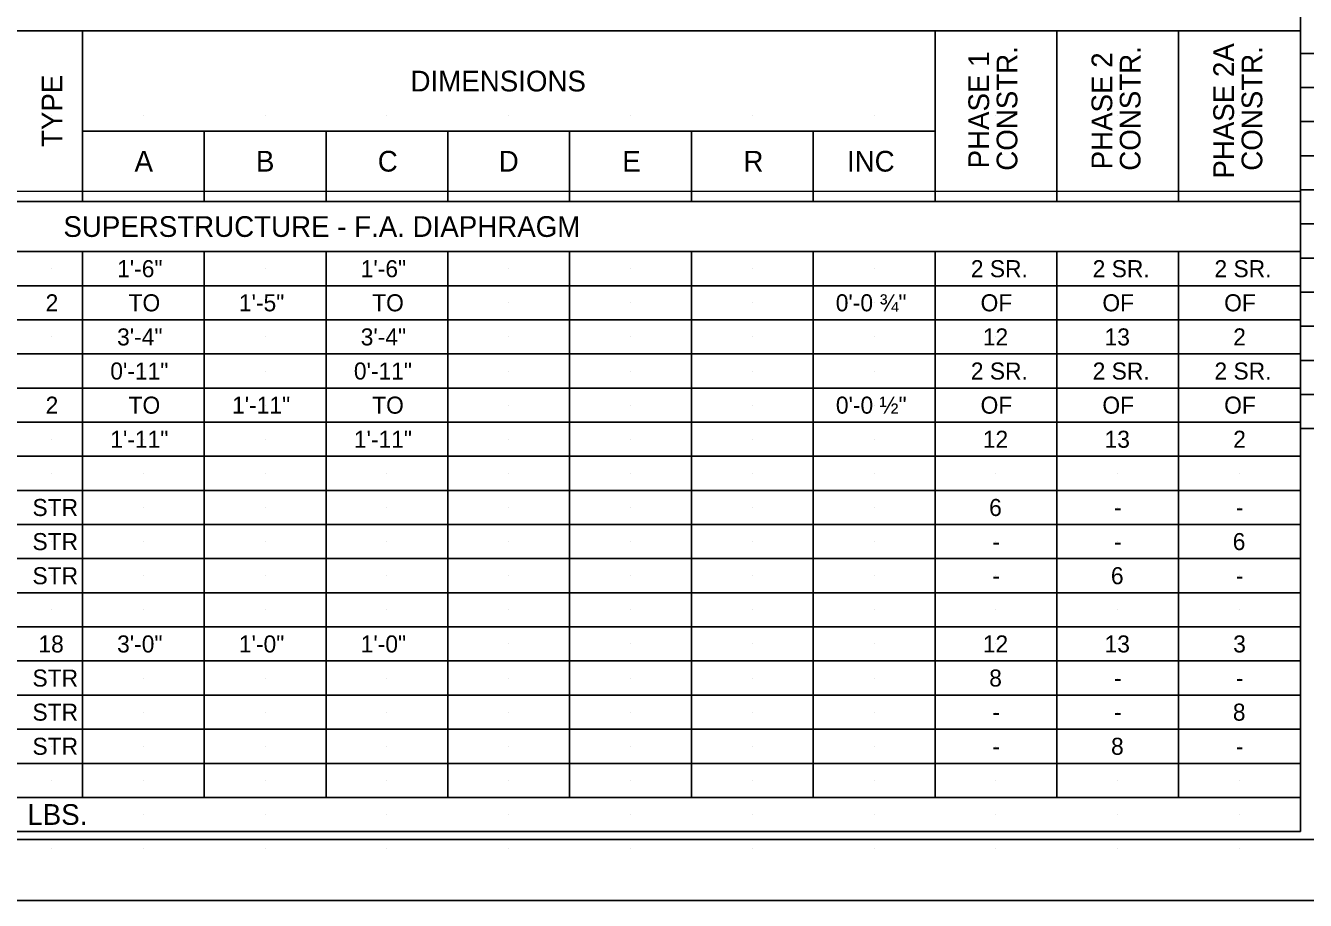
# Model space of a CAD drawing. Extents: x 0 to 34, y 0 to 22.
# Drawn here: x 6.29 to 16.8, y 0 to 7.18 of the extents above; entities that cross this region are included whole.
import ezdxf

# ---------------------------------------------------------------- set-up
doc = ezdxf.new("R2010")
doc.units = 0
for name, color, linetype in [('BR_P_Gen_Text', 7, 'Continuous'), ('SH_Border', 7, 'Continuous'), ('SH_Cut_Line', 7, 'Continuous')]:
    doc.layers.add(name, color=color, linetype=linetype)

msp = doc.modelspace()

# ---------------------------------------------------------------- linework, layer by layer
at = {"layer": 'BR_P_Gen_Text'}
for p, q in [((16.76, 3.872), (16.76, 14.272)), ((1.593, 7.137), (16.76, 7.137)), ((6.76, 5.737), (6.76, 7.137)), ((13.76, 5.737), (13.76, 7.137)), ((14.76, 5.737), (14.76, 7.137)), ((15.76, 5.737), (15.76, 7.137)), ((16.76, 0.565), (16.76, 7.137)), ((16.76, 0.565), (16.76, 7.137)), ((16.76, 6.952), (31.927, 6.952)), ((16.76, 6.672), (31.927, 6.672)), ((6.51, 6.441), (6.51, 6.441)), ((6.51, 6.441), (6.51, 6.441)), ((7.26, 6.441), (7.26, 6.441)), ((8.26, 6.441), (8.26, 6.441)), ((9.26, 6.441), (9.26, 6.441)), ((10.26, 6.441), (10.26, 6.441)), ((11.26, 6.441), (11.26, 6.441)), ((12.26, 6.441), (12.26, 6.441)), ((13.26, 6.441), (13.26, 6.441)), ((14.26, 6.441), (14.26, 6.441)), ((15.26, 6.441), (15.26, 6.441)), ((16.26, 6.441), (16.26, 6.441)), ((6.76, 6.314), (13.76, 6.314)), ((7.76, 5.737), (7.76, 6.314)), ((8.76, 5.737), (8.76, 6.314)), ((9.76, 5.737), (9.76, 6.314)), ((10.76, 5.737), (10.76, 6.314)), ((11.76, 5.737), (11.76, 6.314)), ((12.76, 5.737), (12.76, 6.314)), ((16.76, 6.392), (31.927, 6.392)), ((16.76, 6.112), (31.927, 6.112)), ((1.593, 5.819), (16.76, 5.82)), ((16.76, 5.832), (31.927, 5.832)), ((1.593, 5.737), (16.76, 5.737)), ((7.677, 5.531), (7.677, 5.531)), ((16.76, 5.552), (31.927, 5.552)), ((1.593, 5.325), (16.76, 5.326)), ((6.76, 0.845), (6.76, 5.325)), ((7.76, 0.845), (7.76, 5.325)), ((8.76, 0.845), (8.76, 5.325)), ((9.76, 0.845), (9.76, 5.325)), ((10.76, 0.845), (10.76, 5.325)), ((11.76, 0.845), (11.76, 5.325)), ((12.76, 0.845), (12.76, 5.325)), ((13.76, 0.845), (13.76, 5.325)), ((14.76, 0.845), (14.76, 5.325)), ((15.76, 0.845), (15.76, 5.325)), ((16.76, 5.272), (31.927, 5.272)), ((6.51, 5.185), (6.51, 5.185)), ((7.26, 5.185), (7.26, 5.185)), ((8.26, 5.185), (8.26, 5.185)), ((9.26, 5.185), (9.26, 5.185)), ((10.26, 5.185), (10.26, 5.185)), ((11.26, 5.185), (11.26, 5.185)), ((12.26, 5.185), (12.26, 5.185)), ((13.26, 5.185), (13.26, 5.185)), ((14.26, 5.185), (14.26, 5.185)), ((15.26, 5.185), (15.26, 5.185)), ((16.26, 5.185), (16.26, 5.185)), ((1.593, 5.045), (16.76, 5.045)), ((16.76, 4.992), (31.927, 4.992)), ((6.51, 4.905), (6.51, 4.905)), ((7.26, 4.905), (7.26, 4.905)), ((8.26, 4.905), (8.26, 4.905)), ((9.26, 4.905), (9.26, 4.905)), ((10.26, 4.905), (10.26, 4.905)), ((11.26, 4.905), (11.26, 4.905)), ((12.26, 4.905), (12.26, 4.905)), ((13.26, 4.905), (13.26, 4.905)), ((14.26, 4.905), (14.26, 4.905)), ((15.26, 4.905), (15.26, 4.905)), ((16.26, 4.905), (16.26, 4.905)), ((1.593, 4.765), (16.76, 4.765)), ((6.51, 4.625), (6.51, 4.625)), ((7.26, 4.625), (7.26, 4.625)), ((8.26, 4.625), (8.26, 4.625)), ((9.26, 4.625), (9.26, 4.625)), ((10.26, 4.625), (10.26, 4.625)), ((11.26, 4.625), (11.26, 4.625)), ((12.26, 4.625), (12.26, 4.625)), ((13.26, 4.625), (13.26, 4.625)), ((14.26, 4.625), (14.26, 4.625)), ((15.26, 4.625), (15.26, 4.625)), ((16.26, 4.625), (16.26, 4.625)), ((16.76, 4.712), (31.927, 4.712)), ((1.593, 4.485), (16.76, 4.485)), ((16.76, 4.432), (31.927, 4.432)), ((7.26, 4.345), (7.26, 4.345)), ((8.26, 4.345), (8.26, 4.345)), ((9.26, 4.345), (9.26, 4.345)), ((10.26, 4.345), (10.26, 4.345)), ((11.26, 4.345), (11.26, 4.345)), ((12.26, 4.345), (12.26, 4.345)), ((13.26, 4.345), (13.26, 4.345)), ((14.26, 4.345), (14.26, 4.345)), ((15.26, 4.345), (15.26, 4.345)), ((16.26, 4.345), (16.26, 4.345)), ((1.593, 4.205), (16.76, 4.205)), ((16.76, 4.152), (31.927, 4.152)), ((6.51, 4.065), (6.51, 4.065)), ((7.26, 4.065), (7.26, 4.065)), ((8.26, 4.065), (8.26, 4.065)), ((9.26, 4.065), (9.26, 4.065)), ((10.26, 4.065), (10.26, 4.065)), ((11.26, 4.065), (11.26, 4.065)), ((12.26, 4.065), (12.26, 4.065)), ((13.26, 4.065), (13.26, 4.065)), ((14.26, 4.065), (14.26, 4.065)), ((15.26, 4.065), (15.26, 4.065)), ((16.26, 4.065), (16.26, 4.065)), ((1.593, 3.925), (16.76, 3.925)), ((6.51, 3.785), (6.51, 3.785)), ((7.26, 3.785), (7.26, 3.785)), ((8.26, 3.785), (8.26, 3.785)), ((9.26, 3.785), (9.26, 3.785)), ((10.26, 3.785), (10.26, 3.785)), ((11.26, 3.785), (11.26, 3.785)), ((12.26, 3.785), (12.26, 3.785)), ((13.26, 3.785), (13.26, 3.785)), ((14.26, 3.785), (14.26, 3.785)), ((15.26, 3.785), (15.26, 3.785)), ((16.26, 3.785), (16.26, 3.785)), ((16.76, 3.872), (31.927, 3.872)), ((1.593, 3.645), (16.76, 3.645)), ((6.51, 3.505), (6.51, 3.505)), ((7.26, 3.505), (7.26, 3.505)), ((8.26, 3.505), (8.26, 3.505)), ((9.26, 3.505), (9.26, 3.505)), ((10.26, 3.505), (10.26, 3.505)), ((11.26, 3.505), (11.26, 3.505)), ((12.26, 3.505), (12.26, 3.505)), ((13.26, 3.505), (13.26, 3.505)), ((14.26, 3.505), (14.26, 3.505)), ((15.26, 3.505), (15.26, 3.505)), ((16.26, 3.505), (16.26, 3.505)), ((1.593, 3.365), (16.76, 3.365)), ((6.51, 3.225), (6.51, 3.225)), ((6.51, 3.225), (6.51, 3.225)), ((7.26, 3.225), (7.26, 3.225)), ((7.26, 3.225), (7.26, 3.225)), ((8.26, 3.225), (8.26, 3.225)), ((8.26, 3.225), (8.26, 3.225)), ((9.26, 3.225), (9.26, 3.225)), ((9.26, 3.225), (9.26, 3.225)), ((10.26, 3.225), (10.26, 3.225)), ((10.26, 3.225), (10.26, 3.225)), ((11.26, 3.225), (11.26, 3.225)), ((11.26, 3.225), (11.26, 3.225)), ((12.26, 3.225), (12.26, 3.225)), ((12.26, 3.225), (12.26, 3.225)), ((13.26, 3.225), (13.26, 3.225)), ((13.26, 3.225), (13.26, 3.225)), ((14.26, 3.225), (14.26, 3.225)), ((15.26, 3.225), (15.26, 3.225)), ((16.26, 3.225), (16.26, 3.225)), ((1.593, 3.085), (16.76, 3.085)), ((6.51, 2.945), (6.51, 2.945)), ((6.51, 2.945), (6.51, 2.945)), ((7.26, 2.945), (7.26, 2.945)), ((7.26, 2.945), (7.26, 2.945)), ((8.26, 2.945), (8.26, 2.945)), ((8.26, 2.945), (8.26, 2.945)), ((9.26, 2.945), (9.26, 2.945)), ((9.26, 2.945), (9.26, 2.945)), ((10.26, 2.945), (10.26, 2.945)), ((10.26, 2.945), (10.26, 2.945)), ((11.26, 2.945), (11.26, 2.945)), ((11.26, 2.945), (11.26, 2.945)), ((12.26, 2.945), (12.26, 2.945)), ((12.26, 2.945), (12.26, 2.945)), ((13.26, 2.945), (13.26, 2.945)), ((13.26, 2.945), (13.26, 2.945)), ((14.26, 2.945), (14.26, 2.945)), ((14.26, 2.945), (14.26, 2.945)), ((15.26, 2.945), (15.26, 2.945)), ((15.26, 2.945), (15.26, 2.945)), ((16.26, 2.945), (16.26, 2.945)), ((16.26, 2.945), (16.26, 2.945)), ((1.593, 2.805), (16.76, 2.806)), ((6.51, 2.665), (6.51, 2.665)), ((7.26, 2.665), (7.26, 2.665)), ((8.26, 2.665), (8.26, 2.665)), ((9.26, 2.665), (9.26, 2.665)), ((10.26, 2.665), (10.26, 2.665)), ((11.26, 2.665), (11.26, 2.665)), ((12.26, 2.665), (12.26, 2.665)), ((13.26, 2.665), (13.26, 2.665)), ((14.26, 2.665), (14.26, 2.665)), ((15.26, 2.665), (15.26, 2.665)), ((16.26, 2.665), (16.26, 2.665)), ((1.593, 2.525), (16.76, 2.525)), ((6.51, 2.385), (6.51, 2.385)), ((7.26, 2.385), (7.26, 2.385)), ((8.26, 2.385), (8.26, 2.385)), ((9.26, 2.385), (9.26, 2.385)), ((10.26, 2.385), (10.26, 2.385)), ((11.26, 2.385), (11.26, 2.385)), ((12.26, 2.385), (12.26, 2.385)), ((13.26, 2.385), (13.26, 2.385)), ((14.26, 2.385), (14.26, 2.385)), ((15.26, 2.385), (15.26, 2.385)), ((16.26, 2.385), (16.26, 2.385)), ((1.593, 2.245), (16.76, 2.245)), ((6.51, 2.105), (6.51, 2.105)), ((7.26, 2.105), (7.26, 2.105)), ((8.26, 2.105), (8.26, 2.105)), ((9.26, 2.105), (9.26, 2.105)), ((10.26, 2.105), (10.26, 2.105)), ((11.26, 2.105), (11.26, 2.105)), ((12.26, 2.105), (12.26, 2.105)), ((13.26, 2.105), (13.26, 2.105)), ((14.26, 2.105), (14.26, 2.105)), ((15.26, 2.105), (15.26, 2.105)), ((16.26, 2.105), (16.26, 2.105)), ((1.593, 1.965), (16.76, 1.965)), ((6.51, 1.825), (6.51, 1.825)), ((7.26, 1.825), (7.26, 1.825)), ((8.26, 1.825), (8.26, 1.825)), ((9.26, 1.825), (9.26, 1.825)), ((10.26, 1.825), (10.26, 1.825)), ((11.26, 1.825), (11.26, 1.825)), ((12.26, 1.825), (12.26, 1.825)), ((13.26, 1.825), (13.26, 1.825)), ((14.26, 1.825), (14.26, 1.825)), ((15.26, 1.825), (15.26, 1.825)), ((16.26, 1.825), (16.26, 1.825)), ((1.593, 1.685), (16.76, 1.685)), ((6.51, 1.545), (6.51, 1.545)), ((7.26, 1.545), (7.26, 1.545)), ((8.26, 1.545), (8.26, 1.545)), ((9.26, 1.545), (9.26, 1.545)), ((10.26, 1.545), (10.26, 1.545)), ((11.26, 1.545), (11.26, 1.545)), ((12.26, 1.545), (12.26, 1.545)), ((13.26, 1.545), (13.26, 1.545)), ((14.26, 1.545), (14.26, 1.545)), ((15.26, 1.545), (15.26, 1.545)), ((16.26, 1.545), (16.26, 1.545)), ((1.593, 1.405), (16.76, 1.405)), ((6.51, 1.265), (6.51, 1.265)), ((7.26, 1.265), (7.26, 1.265)), ((8.26, 1.265), (8.26, 1.265)), ((9.26, 1.265), (9.26, 1.265)), ((10.26, 1.265), (10.26, 1.265)), ((11.26, 1.265), (11.26, 1.265)), ((12.26, 1.265), (12.26, 1.265)), ((13.26, 1.265), (13.26, 1.265)), ((14.26, 1.265), (14.26, 1.265)), ((15.26, 1.265), (15.26, 1.265)), ((16.26, 1.265), (16.26, 1.265)), ((1.593, 1.125), (16.76, 1.125)), ((6.51, 0.985), (6.51, 0.985)), ((7.26, 0.985), (7.26, 0.985)), ((8.26, 0.985), (8.26, 0.985)), ((9.26, 0.985), (9.26, 0.985)), ((10.26, 0.985), (10.26, 0.985)), ((11.26, 0.985), (11.26, 0.985)), ((12.26, 0.985), (12.26, 0.985)), ((13.26, 0.985), (13.26, 0.985)), ((14.26, 0.985), (14.26, 0.985)), ((15.26, 0.985), (15.26, 0.985)), ((16.26, 0.985), (16.26, 0.985)), ((1.593, 0.845), (16.76, 0.845)), ((6.51, 0.705), (6.51, 0.705)), ((7.26, 0.705), (7.26, 0.705)), ((8.26, 0.705), (8.26, 0.705)), ((9.26, 0.705), (9.26, 0.705)), ((10.26, 0.705), (10.26, 0.705)), ((11.26, 0.705), (11.26, 0.705)), ((12.26, 0.705), (12.26, 0.705)), ((13.26, 0.705), (13.26, 0.705)), ((14.26, 0.705), (14.26, 0.705)), ((15.26, 0.705), (15.26, 0.705)), ((16.26, 0.705), (16.26, 0.705)), ((1.593, 0.565), (16.76, 0.565)), ((6.51, 0.425), (6.51, 0.425)), ((6.51, 0.425), (6.51, 0.425)), ((7.26, 0.425), (7.26, 0.425)), ((7.26, 0.425), (7.26, 0.425)), ((8.26, 0.425), (8.26, 0.425)), ((8.26, 0.425), (8.26, 0.425)), ((9.26, 0.425), (9.26, 0.425)), ((9.26, 0.425), (9.26, 0.425)), ((10.26, 0.425), (10.26, 0.425)), ((10.26, 0.425), (10.26, 0.425)), ((11.26, 0.425), (11.26, 0.425)), ((11.26, 0.425), (11.26, 0.425)), ((12.26, 0.425), (12.26, 0.425)), ((12.26, 0.425), (12.26, 0.425)), ((13.26, 0.425), (13.26, 0.425)), ((13.26, 0.425), (13.26, 0.425)), ((14.26, 0.425), (14.26, 0.425)), ((15.26, 0.425), (15.26, 0.425)), ((16.26, 0.425), (16.26, 0.425))]:
    msp.add_line(p, q, dxfattribs=at)
at = {"layer": 'SH_Border'}
msp.add_lwpolyline([(1.5, 21.5), (33.5, 21.5), (33.5, 0.5), (1.5, 0.5)], close=True, dxfattribs=at)
at = {"layer": 'SH_Cut_Line'}
msp.add_lwpolyline([(0, 0), (34, 0), (34, 22), (0, 22)], close=True, dxfattribs=at)

# ---------------------------------------------------------------- texts
at = {"layer": 'BR_P_Gen_Text'}
for s, p in [('PHASE 1', (14.204, 6.008)), ('CONSTR.', (14.436, 5.989)), ('PHASE 2', (15.215, 6)), ('CONSTR.', (15.447, 5.989)), ('PHASE 2A', (16.215, 5.924)), ('CONSTR.', (16.447, 5.989)), ('TYPE', (6.595, 6.184))]:
    msp.add_text(s, height=0.17, rotation=90, dxfattribs=at).set_placement(p)
for s, height, p in [('DIMENSIONS', 0.17, (9.454, 6.64)), ('A', 0.17, (7.188, 5.982)), ('B', 0.17, (8.185, 5.982)), ('C', 0.17, (9.185, 5.982)), ('D', 0.17, (10.178, 5.982)), ('E', 0.17, (11.192, 5.982)), ('R', 0.17, (12.187, 5.982)), ('INC', 0.17, (13.037, 5.982)), ('SUPERSTRUCTURE - F.A. DIAPHRAGM', 0.17, (6.604, 5.446)), ('1\'-6"', 0.14, (7.045, 5.115)), ('1\'-6"', 0.14, (9.045, 5.115)), ('2 SR.', 0.14, (14.054, 5.115)), ('2 SR.', 0.14, (15.054, 5.115)), ('2 SR.', 0.14, (16.054, 5.115)), ('2', 0.14, (6.458, 4.835)), ('TO', 0.14, (7.139, 4.835)), ('1\'-5"', 0.14, (8.045, 4.835)), ('TO', 0.14, (9.139, 4.835)), ('0\'-0 ¾"', 0.14, (12.945, 4.835)), ('OF', 0.14, (14.134, 4.835)), ('OF', 0.14, (15.134, 4.835)), ('OF', 0.14, (16.134, 4.835)), ('3\'-4"', 0.14, (7.045, 4.555)), ('3\'-4"', 0.14, (9.045, 4.555)), ('12', 0.14, (14.152, 4.555)), ('13', 0.14, (15.152, 4.555)), ('2', 0.14, (16.208, 4.555)), ('0\'-11"', 0.14, (6.989, 4.275)), ('0\'-11"', 0.14, (8.989, 4.275)), ('2 SR.', 0.14, (14.054, 4.275)), ('2 SR.', 0.14, (15.054, 4.275)), ('2 SR.', 0.14, (16.054, 4.275)), ('2', 0.14, (6.458, 3.995)), ('TO', 0.14, (7.139, 3.995)), ('1\'-11"', 0.14, (7.989, 3.995)), ('TO', 0.14, (9.139, 3.995)), ('0\'-0 ½"', 0.14, (12.946, 3.995)), ('OF', 0.14, (14.134, 3.995)), ('OF', 0.14, (15.134, 3.995)), ('OF', 0.14, (16.134, 3.995)), ('1\'-11"', 0.14, (6.989, 3.715)), ('1\'-11"', 0.14, (8.989, 3.715)), ('12', 0.14, (14.152, 3.715)), ('13', 0.14, (15.152, 3.715)), ('2', 0.14, (16.208, 3.715)), ('STR', 0.14, (6.35, 3.155)), ('6', 0.14, (14.204, 3.155)), ('-', 0.14, (15.23, 3.155)), ('-', 0.14, (16.23, 3.155)), ('STR', 0.14, (6.35, 2.875)), ('6', 0.14, (16.204, 2.875)), ('-', 0.14, (14.23, 2.875)), ('-', 0.14, (15.23, 2.875)), ('STR', 0.14, (6.35, 2.595)), ('6', 0.14, (15.204, 2.595)), ('-', 0.14, (14.23, 2.595)), ('-', 0.14, (16.23, 2.595)), ('18', 0.14, (6.399, 2.035)), ('3\'-0"', 0.14, (7.045, 2.035)), ('1\'-0"', 0.14, (8.045, 2.035)), ('1\'-0"', 0.14, (9.045, 2.035)), ('12', 0.14, (14.152, 2.035)), ('13', 0.14, (15.152, 2.035)), ('3', 0.14, (16.208, 2.035)), ('STR', 0.14, (6.35, 1.755)), ('8', 0.14, (14.205, 1.755)), ('-', 0.14, (15.23, 1.755)), ('-', 0.14, (16.23, 1.755)), ('STR', 0.14, (6.35, 1.475)), ('8', 0.14, (16.205, 1.475)), ('-', 0.14, (14.23, 1.475)), ('-', 0.14, (15.23, 1.475)), ('STR', 0.14, (6.35, 1.195)), ('8', 0.14, (15.205, 1.195)), ('-', 0.14, (14.23, 1.195)), ('-', 0.14, (16.23, 1.195)), ('LBS.', 0.17, (6.308, 0.62))]:
    msp.add_text(s, height=height, dxfattribs=at).set_placement(p)

doc.saveas('drawing.dxf')
